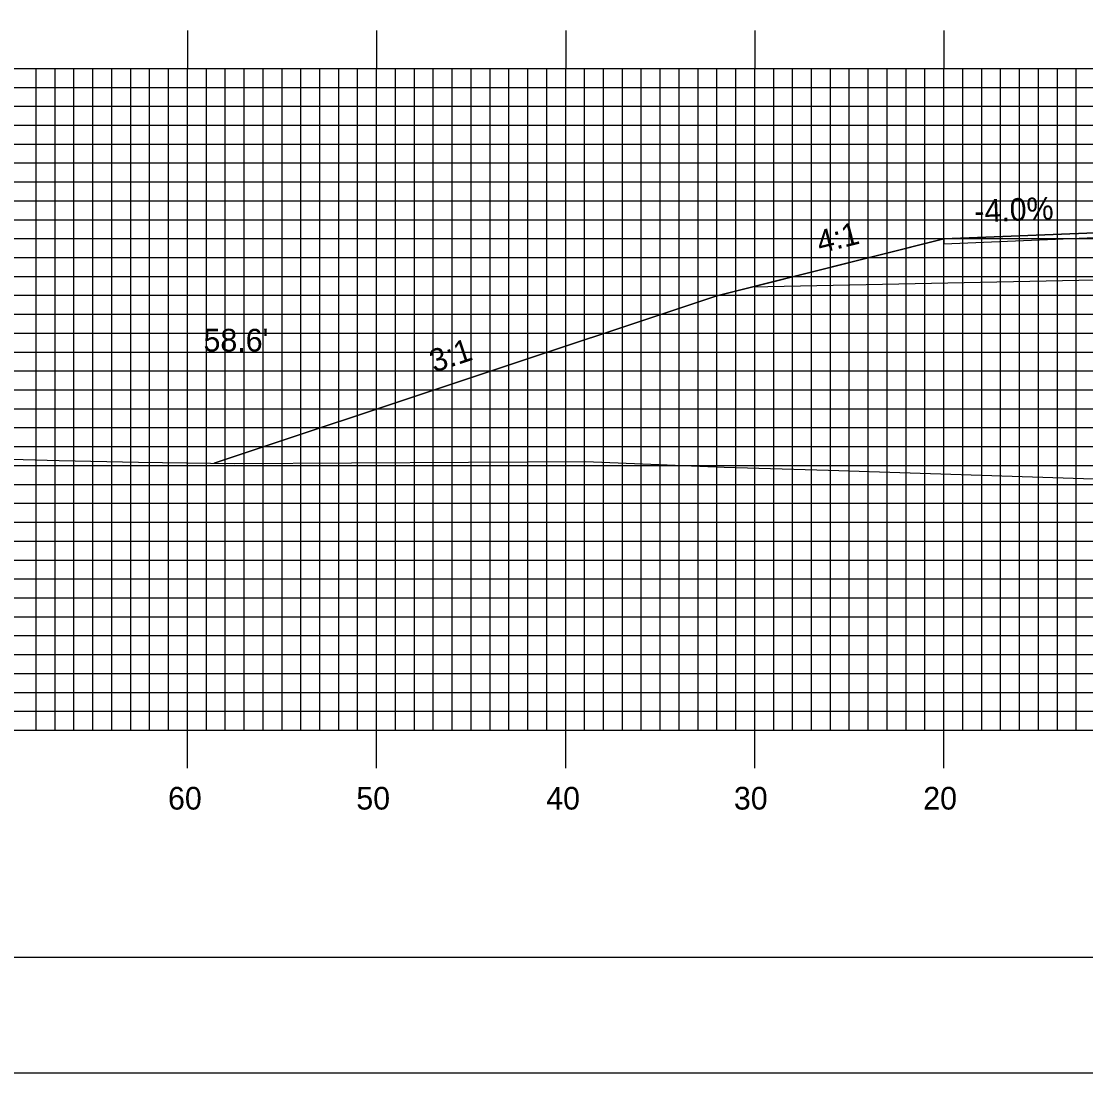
# Model space of a CAD drawing. Extents: x 1807045 to 1807388, y 442591 to 442811.
# Drawn here: x 1807142 to 1807198.3, y 442590.5 to 442646.2 of the extents above; entities that cross this region are included whole.
import ezdxf

# ---------------------------------------------------------------- set-up
doc = ezdxf.new("R2010")
doc.units = 0
for name, color, linetype in [('ANNOTATION', 7, 'Continuous'), ('BORDER', 7, 'Continuous'), ('D_Roadway_Centerline', 7, 'Continuous'), ('D_Roadway_Edge_Shoulder', 7, 'Continuous'), ('D_Roadway_SlopeLines', 7, 'Continuous'), ('D_Roadway_SubGrade', 7, 'Continuous'), ('D_Text_Standard', 7, 'Continuous'), ('H_V ANNOTATION', 7, 'Continuous'), ('MAJOR', 7, 'Continuous'), ('MINOR', 7, 'Continuous'), ('PLOT BOUNDARY', 7, 'Continuous'), ('S_Roadway_Centerline', 7, 'Continuous')]:
    doc.layers.add(name, color=color, linetype=linetype)

msp = doc.modelspace()

# ---------------------------------------------------------------- linework, layer by layer
at = {"layer": 'BORDER'}
msp.add_lwpolyline([(1807061.159, 442596.665), (1807381.159, 442596.665), (1807381.159, 442806.665), (1807061.159, 442806.665)], close=True, dxfattribs=at)
at = {"layer": 'D_Roadway_Centerline'}
msp.add_lwpolyline([(1807152.17, 442622.783), (1807178.759, 442631.646), (1807180.585, 442632.103), (1807190.759, 442634.646), (1807198.759, 442634.966), (1807210.759, 442635.206), (1807222.759, 442634.966), (1807230.759, 442634.646), (1807240.933, 442632.103), (1807242.759, 442631.646), (1807272.573, 442621.708)], dxfattribs=at)
at = {"layer": 'D_Roadway_Edge_Shoulder'}
msp.add_lwpolyline([(1807198.759, 442634.966), (1807190.759, 442634.646), (1807190.759, 442634.396), (1807198.759, 442634.716)], close=True, dxfattribs=at)
at = {"layer": 'D_Roadway_SlopeLines'}
msp.add_lwpolyline([(1807190.759, 442634.646), (1807178.759, 442631.646), (1807152.17, 442622.783)], dxfattribs=at)
at = {"layer": 'D_Roadway_SubGrade'}
msp.add_lwpolyline([(1807198.759, 442632.466), (1807180.585, 442632.103), (1807190.759, 442634.646), (1807190.759, 442634.396), (1807198.759, 442634.716), (1807210.759, 442634.956), (1807222.759, 442634.716), (1807230.759, 442634.396), (1807230.759, 442634.646), (1807240.933, 442632.103), (1807222.759, 442632.466), (1807210.759, 442632.706)], close=True, dxfattribs=at)
at = {"layer": 'MAJOR'}
for p, q in [((1807150.759, 442645.669), (1807150.759, 442643.665)), ((1807160.759, 442645.669), (1807160.759, 442643.665)), ((1807170.759, 442645.669), (1807170.759, 442643.665)), ((1807180.759, 442645.669), (1807180.759, 442643.665)), ((1807190.759, 442645.669), (1807190.759, 442643.665)), ((1807070.759, 442643.665), (1807350.759, 442643.665)), ((1807070.759, 442643.665), (1807350.759, 442643.665)), ((1807150.759, 442608.665), (1807150.759, 442643.665)), ((1807160.759, 442608.665), (1807160.759, 442643.665)), ((1807170.759, 442608.665), (1807170.759, 442643.665)), ((1807180.759, 442608.665), (1807180.759, 442643.665)), ((1807190.759, 442608.665), (1807190.759, 442643.665)), ((1807070.759, 442638.665), (1807350.759, 442638.665)), ((1807070.759, 442633.665), (1807350.759, 442633.665)), ((1807070.759, 442628.665), (1807350.759, 442628.665)), ((1807070.759, 442623.665), (1807350.759, 442623.665)), ((1807070.759, 442618.665), (1807350.759, 442618.665)), ((1807070.759, 442613.665), (1807350.759, 442613.665)), ((1807070.759, 442608.665), (1807350.759, 442608.665)), ((1807070.759, 442608.665), (1807350.759, 442608.665)), ((1807150.759, 442606.661), (1807150.759, 442608.665)), ((1807160.759, 442606.661), (1807160.759, 442608.665)), ((1807170.759, 442606.661), (1807170.759, 442608.665)), ((1807180.759, 442606.661), (1807180.759, 442608.665)), ((1807190.759, 442606.661), (1807190.759, 442608.665))]:
    msp.add_line(p, q, dxfattribs=at)
at = {"layer": 'MINOR'}
for p, q in [((1807142.759, 442608.665), (1807142.759, 442643.665)), ((1807143.759, 442608.665), (1807143.759, 442643.665)), ((1807144.759, 442608.665), (1807144.759, 442643.665)), ((1807145.759, 442608.665), (1807145.759, 442643.665)), ((1807146.759, 442608.665), (1807146.759, 442643.665)), ((1807147.759, 442608.665), (1807147.759, 442643.665)), ((1807148.759, 442608.665), (1807148.759, 442643.665)), ((1807149.759, 442608.665), (1807149.759, 442643.665)), ((1807151.759, 442608.665), (1807151.759, 442643.665)), ((1807152.759, 442608.665), (1807152.759, 442643.665)), ((1807153.759, 442608.665), (1807153.759, 442643.665)), ((1807154.759, 442608.665), (1807154.759, 442643.665)), ((1807155.759, 442608.665), (1807155.759, 442643.665)), ((1807156.759, 442608.665), (1807156.759, 442643.665)), ((1807157.759, 442608.665), (1807157.759, 442643.665)), ((1807158.759, 442608.665), (1807158.759, 442643.665)), ((1807159.759, 442608.665), (1807159.759, 442643.665)), ((1807161.759, 442608.665), (1807161.759, 442643.665)), ((1807162.759, 442608.665), (1807162.759, 442643.665)), ((1807163.759, 442608.665), (1807163.759, 442643.665)), ((1807164.759, 442608.665), (1807164.759, 442643.665)), ((1807165.759, 442608.665), (1807165.759, 442643.665)), ((1807166.759, 442608.665), (1807166.759, 442643.665)), ((1807167.759, 442608.665), (1807167.759, 442643.665)), ((1807168.759, 442608.665), (1807168.759, 442643.665)), ((1807169.759, 442608.665), (1807169.759, 442643.665)), ((1807171.759, 442608.665), (1807171.759, 442643.665)), ((1807172.759, 442608.665), (1807172.759, 442643.665)), ((1807173.759, 442608.665), (1807173.759, 442643.665)), ((1807174.759, 442608.665), (1807174.759, 442643.665)), ((1807175.759, 442608.665), (1807175.759, 442643.665)), ((1807176.759, 442608.665), (1807176.759, 442643.665)), ((1807177.759, 442608.665), (1807177.759, 442643.665)), ((1807178.759, 442608.665), (1807178.759, 442643.665)), ((1807179.759, 442608.665), (1807179.759, 442643.665)), ((1807181.759, 442608.665), (1807181.759, 442643.665)), ((1807182.759, 442608.665), (1807182.759, 442643.665)), ((1807183.759, 442608.665), (1807183.759, 442643.665)), ((1807184.759, 442608.665), (1807184.759, 442643.665)), ((1807185.759, 442608.665), (1807185.759, 442643.665)), ((1807186.759, 442608.665), (1807186.759, 442643.665)), ((1807187.759, 442608.665), (1807187.759, 442643.665)), ((1807188.759, 442608.665), (1807188.759, 442643.665)), ((1807189.759, 442608.665), (1807189.759, 442643.665)), ((1807191.759, 442608.665), (1807191.759, 442643.665)), ((1807192.759, 442608.665), (1807192.759, 442643.665)), ((1807193.759, 442608.665), (1807193.759, 442643.665)), ((1807194.759, 442608.665), (1807194.759, 442643.665)), ((1807195.759, 442608.665), (1807195.759, 442643.665)), ((1807196.759, 442608.665), (1807196.759, 442643.665)), ((1807197.759, 442608.665), (1807197.759, 442643.665)), ((1807070.759, 442642.665), (1807350.759, 442642.665)), ((1807070.759, 442641.665), (1807350.759, 442641.665)), ((1807070.759, 442640.665), (1807350.759, 442640.665)), ((1807070.759, 442639.665), (1807350.759, 442639.665)), ((1807070.759, 442637.665), (1807350.759, 442637.665)), ((1807070.759, 442636.665), (1807350.759, 442636.665)), ((1807070.759, 442635.665), (1807350.759, 442635.665)), ((1807070.759, 442634.665), (1807350.759, 442634.665)), ((1807070.759, 442632.665), (1807350.759, 442632.665)), ((1807070.759, 442631.665), (1807350.759, 442631.665)), ((1807070.759, 442630.665), (1807350.759, 442630.665)), ((1807070.759, 442629.665), (1807350.759, 442629.665)), ((1807070.759, 442627.665), (1807350.759, 442627.665)), ((1807070.759, 442626.665), (1807350.759, 442626.665)), ((1807070.759, 442625.665), (1807350.759, 442625.665)), ((1807070.759, 442624.665), (1807350.759, 442624.665)), ((1807070.759, 442622.665), (1807350.759, 442622.665)), ((1807070.759, 442621.665), (1807350.759, 442621.665)), ((1807070.759, 442620.665), (1807350.759, 442620.665)), ((1807070.759, 442619.665), (1807350.759, 442619.665)), ((1807070.759, 442617.665), (1807350.759, 442617.665)), ((1807070.759, 442616.665), (1807350.759, 442616.665)), ((1807070.759, 442615.665), (1807350.759, 442615.665)), ((1807070.759, 442614.665), (1807350.759, 442614.665)), ((1807070.759, 442612.665), (1807350.759, 442612.665)), ((1807070.759, 442611.665), (1807350.759, 442611.665)), ((1807070.759, 442610.665), (1807350.759, 442610.665)), ((1807070.759, 442609.665), (1807350.759, 442609.665))]:
    msp.add_line(p, q, dxfattribs=at)
at = {"layer": 'PLOT BOUNDARY'}
msp.add_lwpolyline([(1807044.972, 442590.547), (1807384.972, 442590.547), (1807384.972, 442810.547), (1807044.972, 442810.547)], close=True, dxfattribs=at)
at = {"layer": 'S_Roadway_Centerline'}
msp.add_lwpolyline([(1807070.759, 442624.588), (1807076.532, 442624.486), (1807090.473, 442624.051), (1807101.359, 442623.602), (1807101.616, 442623.6), (1807102.663, 442623.583), (1807121.922, 442623.53), (1807124.249, 442623.473), (1807143.984, 442622.932), (1807148.174, 442622.845), (1807153.239, 442622.767), (1807171.802, 442622.883), (1807179.132, 442622.578), (1807184.653, 442622.424), (1807206.24, 442621.713), (1807206.839, 442621.699), (1807232.064, 442621.65), (1807241.46, 442621.516), (1807249.476, 442621.7), (1807259.21, 442621.932), (1807269.785, 442621.757), (1807281.757, 442621.548)], dxfattribs=at)

# ---------------------------------------------------------------- texts
at = {"layer": 'ANNOTATION'}
for s, rotation, p in [('-4.0%', 2.2906, (1807192.391, 442635.513)), ('4:1', 14.0362, (1807184.207, 442633.87)), ('3:1', 18.4348, (1807163.803, 442627.569))]:
    msp.add_text(s, height=1.2, rotation=rotation, dxfattribs=at).set_placement(p)
at = {"layer": 'D_Text_Standard'}
msp.add_text("58.6'", height=1.2, dxfattribs=at).set_placement((1807151.609, 442628.692))
at = {"layer": 'H_V ANNOTATION'}
for s, p in [('60', (1807149.731, 442604.465)), ('50', (1807159.688, 442604.465)), ('40', (1807169.731, 442604.465)), ('30', (1807179.656, 442604.465)), ('20', (1807189.667, 442604.465))]:
    msp.add_text(s, height=1.2, dxfattribs=at).set_placement(p)

doc.saveas('drawing.dxf')
